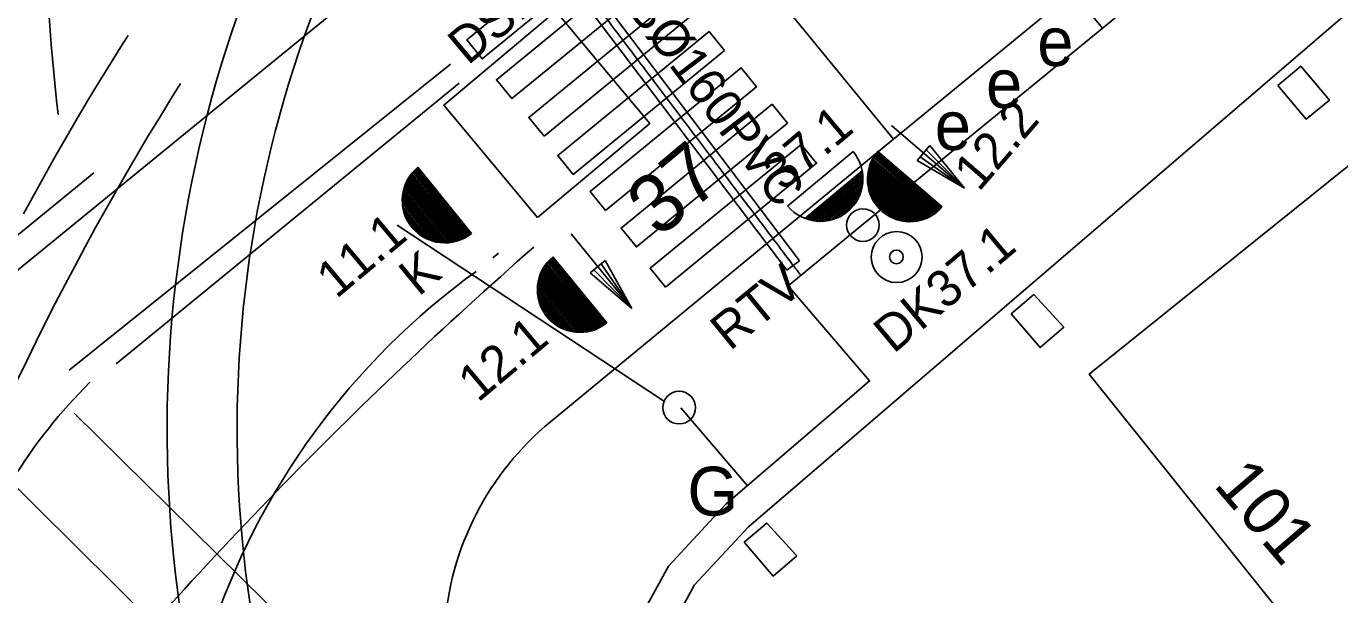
# Model space of a CAD drawing. Extents: x 81617 to 82144, y 454649 to 455150.
# Drawn here: x 81850.79 to 81877.73, y 454892.85 to 454904.5 of the extents above; entities that cross this region are included whole.
import ezdxf

# ---------------------------------------------------------------- set-up
doc = ezdxf.new("R2010")
doc.units = 0
for name, color, linetype in [('B-WE-OG-TOPOGRAFIE-G', 7, 'Continuous'), ('B-WE-VW-MARKERING-G', 7, 'Continuous'), ('N-OI-KL-VRI_KABELGEUL-G', 7, 'Continuous'), ('N-OI-KL-VRI_LUS_DETECTIE_SELECTIEF-G', 7, 'Continuous'), ('N-OI-KL-VRI_LUS_DETECTIE_SELECTIEF-T18', 7, 'Continuous'), ('N-OI-KL-VRI_MANTELBUIS-G', 7, 'Continuous'), ('N-OI-KL-VRI_MANTELBUIS-T18', 7, 'Continuous'), ('N-WE-VW-VRI_ARMATUUR-S', 7, 'Continuous'), ('N-WE-VW-VRI_ARMATUUR-T18', 7, 'Continuous'), ('N-WE-VW-VRI_LIGGER-G', 7, 'Continuous'), ('N-WE-VW-VRI_MAST-S', 7, 'Continuous'), ('N-WE-VW-VRI_RICHTINGNUMMER-T25', 7, 'Continuous')]:
    doc.layers.add(name, color=color, linetype=linetype)

msp = doc.modelspace()

# ---------------------------------------------------------------- linework, layer by layer
at = {"layer": 'B-WE-OG-TOPOGRAFIE-G'}
for p, q in [((81881.705, 454912.935), (81868.159, 454901.847)), ((81884.598, 454910.533), (81865.6, 454894.244)), ((81865.6, 454894.244), (81864.496, 454893.051)), ((81864.496, 454893.051), (81863.715, 454891.626))]:
    msp.add_line(p, q, dxfattribs=at)
for points in [[(81905.797, 454910.826), (81895.907, 454902.577), (81894.356, 454904.415), (81878.095, 454890.513), (81872.591, 454897.372), (81877.883, 454901.619), (81888.858, 454911.006), (81888.57, 454911.351)], [(81852.878, 454904.311), (81852.766, 454904.134), (81852.528, 454903.754), (81852.294, 454903.373), (81852.062, 454902.99), (81851.834, 454902.607), (81851.608, 454902.221), (81851.383, 454901.831), (81850.948, 454901.054), (81850.733, 454900.659)], [(81876.463, 454903.285), (81876.929, 454903.679), (81877.517, 454902.984), (81877.039, 454902.598), (81876.463, 454903.285)], [(81853.953, 454903.327), (81853.748, 454902.998), (81853.519, 454902.626), (81853.293, 454902.252), (81853.07, 454901.877), (81852.849, 454901.5), (81852.631, 454901.122), (81852.204, 454900.36), (81851.995, 454899.977), (81851.789, 454899.592), (81851.585, 454899.206), (81851.384, 454898.818), (81851.186, 454898.429), (81850.991, 454898.038), (81850.799, 454897.646), (81850.61, 454897.253), (81850.423, 454896.858), (81850.24, 454896.461), (81850.058, 454896.06), (81849.702, 454895.254), (81849.356, 454894.442), (81849.019, 454893.625), (81848.691, 454892.804)], [(81868.159, 454901.847), (81861.541, 454896.395)], [(81871.452, 454899), (81872.069, 454898.33), (81871.583, 454897.914), (81870.991, 454898.605), (81871.452, 454899)], [(81865.517, 454893.926), (81865.982, 454894.319), (81866.594, 454893.648), (81866.107, 454893.233), (81865.517, 454893.926)]]:
    msp.add_lwpolyline(points, dxfattribs=at)
for centre, radius, start, end in [((81879.363, 454896.235), 25.685, 143.017, 194.1581), ((81879.363, 454896.235), 24.25, 143.017, 194.1581), ((81865.356, 454891.764), 6, 129.48, 223.0627)]:
    msp.add_arc(centre, radius, start, end, dxfattribs=at)
at = {"layer": 'B-WE-VW-MARKERING-G'}
for p, q in [((81868.576, 454902.188), (81862.556, 454909.542)), ((81852.173, 454901.495), (81847.644, 454897.796)), ((81860.476, 454899.85), (81860.356, 454899.752)), ((81859.578, 454888.893), (81851.77, 454896.571)), ((81860.984, 454884.776), (81850.084, 454895.546))]:
    msp.add_line(p, q, dxfattribs=at)
for points in [[(81863.241, 454906.37), (81860.141, 454903.832), (81859.824, 454904.219), (81862.925, 454906.757)], [(81863.851, 454905.554), (81860.75, 454903.017), (81860.433, 454903.404), (81863.534, 454905.941)], [(81861.412, 454902.246), (81864.512, 454904.784), (81864.195, 454905.17), (81861.095, 454902.633)], [(81865.109, 454904.003), (81862.009, 454901.465), (81861.692, 454901.852), (81864.793, 454904.39)], [(81862.669, 454900.723), (81865.769, 454903.261), (81865.453, 454903.648), (81862.352, 454901.11)], [(81866.405, 454902.515), (81863.305, 454899.977), (81862.988, 454900.364), (81866.088, 454902.901)], [(81863.9, 454899.153), (81867, 454901.691), (81866.684, 454902.078), (81863.583, 454899.54)]]:
    msp.add_lwpolyline(points, close=True, dxfattribs=at)
for points in [[(81857.965, 454905.504), (81847.346, 454896.846)], [(81859.492, 454903.724), (81851.668, 454897.452)], [(81859.666, 454903.336), (81852.632, 454897.581)]]:
    msp.add_lwpolyline(points, dxfattribs=at)
for centre, radius, start, end in [((81891.158, 454907.365), 39.987, 173.5249, 186.7077), ((81920.451, 454832.229), 90, 131.17648, 140.46049), ((81868.809, 454887.325), 15, 125.8906, 161.8334), ((81859.635, 454889.585), 10.719, 134.6953, 161.9917)]:
    msp.add_arc(centre, radius, start, end, dxfattribs=at)
at = {"layer": 'N-OI-KL-VRI_KABELGEUL-G'}
msp.add_line((81872.26, 454905.203), (81872.866, 454904.461), dxfattribs=at)
for points in [[(81868.039, 454900.514), (81884.291, 454913.804)], [(81868.039, 454900.514), (81866.417, 454899.179)], [(81866.417, 454899.179), (81868.086, 454897.232), (81867.77, 454896.961), (81865.148, 454894.713), (81863.965, 454893.434), (81863.103, 454891.862), (81862.654, 454889.993), (81862.638, 454888.354), (81862.929, 454886.524), (81867.816, 454881.297)], [(81864.213, 454896.678), (81865.58, 454895.083)]]:
    msp.add_lwpolyline(points, dxfattribs=at)
msp.add_open_spline([(81966.954, 454994.044), (81954.516, 454984.42), (81942.079, 454974.796), (81941.008, 454974.125), (81939.937, 454973.455), (81933.631, 454968.575), (81927.325, 454963.696), (81926.798, 454963.288), (81926.621, 454962.646), (81926.355, 454961.682), (81926.09, 454960.718), (81925.901, 454960.035), (81925.325, 454959.623), (81922.434, 454957.557), (81919.543, 454955.49), (81917.87, 454954.23), (81916.197, 454952.97), (81913.406, 454950.849), (81910.615, 454948.728), (81908.564, 454947.145), (81906.513, 454945.562), (81905.944, 454945.123), (81905.225, 454945.147), (81904.815, 454945.16), (81904.405, 454945.174), (81903.693, 454945.197), (81903.126, 454944.765), (81893.683, 454937.565), (81884.239, 454930.365), (81883.469, 454929.731), (81882.698, 454929.096), (81879.285, 454926.178), (81875.872, 454923.259), (81872.421, 454920.321), (81868.97, 454917.382), (81867.082, 454915.724), (81865.195, 454914.067), (81863.45, 454912.271), (81861.704, 454910.475), (81860.838, 454909.482), (81859.972, 454908.49), (81859.86, 454908.361), (81859.97, 454908.23), (81860.094, 454908.077), (81860.218, 454907.925), (81863.368, 454903.762), (81866.518, 454899.599), (81866.598, 454899.497), (81866.679, 454899.395)], degree=4, dxfattribs=at)
at = {"layer": 'N-OI-KL-VRI_LUS_DETECTIE_SELECTIEF-G'}
msp.add_lwpolyline([(81861.276, 454900.581), (81859.351, 454902.881), (81861.651, 454904.806), (81863.578, 454902.506)], close=True, dxfattribs=at)
at = {"layer": 'N-OI-KL-VRI_MANTELBUIS-G'}
msp.add_lwpolyline([(81866.39, 454899.502), (81860.17, 454907.723), (81860.426, 454907.917), (81866.646, 454899.695), (81866.39, 454899.502)], dxfattribs=at)
at = {"layer": 'N-WE-VW-VRI_ARMATUUR-S'}
for p, q in [((81868.537, 454902.464), (81870.032, 454901.18)), ((81869.063, 454901.747), (81869.322, 454902.054)), ((81869.249, 454901.967), (81870.032, 454901.18)), ((81869.322, 454902.054), (81870.032, 454901.18)), ((81867.75, 454901.932), (81866.404, 454900.815)), ((81869.368, 454900.62), (81868.108, 454901.702)), ((81869.394, 454900.637), (81868.122, 454901.732)), ((81869.422, 454900.655), (81868.135, 454901.758)), ((81869.445, 454900.672), (81868.148, 454901.785)), ((81869.469, 454900.691), (81868.164, 454901.814)), ((81869.493, 454900.713), (81868.18, 454901.838)), ((81869.515, 454900.734), (81868.195, 454901.864)), ((81869.536, 454900.755), (81868.214, 454901.887)), ((81869.558, 454900.776), (81868.232, 454901.911)), ((81869.578, 454900.798), (81868.251, 454901.937)), ((81870.032, 454901.18), (81869.063, 454901.747)), ((81869.127, 454901.823), (81870.032, 454901.18)), ((81859.713, 454900.13), (81858.658, 454901.435)), ((81859.744, 454900.143), (81858.675, 454901.459)), ((81859.771, 454900.157), (81858.694, 454901.483)), ((81859.796, 454900.17), (81858.715, 454901.508)), ((81859.824, 454900.186), (81858.734, 454901.529)), ((81859.85, 454900.203), (81858.755, 454901.55)), ((81859.875, 454900.219), (81858.776, 454901.572)), ((81859.899, 454900.238), (81858.801, 454901.593)), ((81859.923, 454900.255), (81858.823, 454901.613)), ((81867.934, 454901.539), (81866.756, 454900.563)), ((81867.941, 454901.505), (81866.788, 454900.55)), ((81867.946, 454901.47), (81866.821, 454900.538)), ((81867.949, 454901.433), (81866.856, 454900.529)), ((81869.12, 454900.519), (81868.045, 454901.442)), ((81869.156, 454900.528), (81868.049, 454901.478)), ((81869.189, 454900.539), (81868.053, 454901.514)), ((81869.222, 454900.55), (81868.061, 454901.546)), ((81869.253, 454900.563), (81868.069, 454901.579)), ((81869.284, 454900.576), (81868.077, 454901.612)), ((81869.314, 454900.589), (81868.087, 454901.643)), ((81869.344, 454900.605), (81868.099, 454901.67)), ((81859.423, 454900.062), (81858.53, 454901.164)), ((81859.46, 454900.065), (81858.54, 454901.199)), ((81859.495, 454900.069), (81858.552, 454901.233)), ((81859.529, 454900.074), (81858.566, 454901.263)), ((81859.563, 454900.082), (81858.578, 454901.295)), ((81859.594, 454900.089), (81858.593, 454901.326)), ((81859.626, 454900.098), (81858.608, 454901.354)), ((81859.655, 454900.106), (81858.622, 454901.381)), ((81859.686, 454900.119), (81858.639, 454901.408)), ((81867.952, 454901.396), (81866.894, 454900.521)), ((81867.951, 454901.356), (81866.931, 454900.513)), ((81867.948, 454901.317), (81866.972, 454900.506)), ((81867.944, 454901.275), (81867.015, 454900.5)), ((81867.939, 454901.23), (81867.059, 454900.5)), ((81867.932, 454901.182), (81867.107, 454900.502)), ((81869.083, 454900.509), (81868.042, 454901.404)), ((81869.005, 454900.499), (81868.042, 454901.326)), ((81869.046, 454900.503), (81868.043, 454901.365)), ((81868.963, 454900.496), (81868.044, 454901.282)), ((81868.92, 454900.493), (81868.052, 454901.238)), ((81868.87, 454900.494), (81868.059, 454901.19)), ((81859.172, 454900.083), (81858.5, 454900.912)), ((81859.264, 454900.068), (81858.501, 454901.006)), ((81859.22, 454900.074), (81858.501, 454900.962)), ((81859.307, 454900.063), (81858.508, 454901.049)), ((81859.347, 454900.061), (81858.514, 454901.089)), ((81859.385, 454900.061), (81858.522, 454901.127)), ((81867.916, 454901.134), (81867.156, 454900.505)), ((81867.901, 454901.081), (81867.212, 454900.511)), ((81867.877, 454901.022), (81867.275, 454900.521)), ((81867.845, 454900.957), (81867.345, 454900.543)), ((81868.821, 454900.499), (81868.071, 454901.143)), ((81868.764, 454900.509), (81868.089, 454901.087)), ((81868.705, 454900.52), (81868.109, 454901.028)), ((81868.634, 454900.541), (81868.14, 454900.962)), ((81868.547, 454900.576), (81868.187, 454900.882)), ((81859.125, 454900.097), (81858.503, 454900.865)), ((81859.07, 454900.114), (81858.508, 454900.807)), ((81859.014, 454900.138), (81858.519, 454900.745)), ((81858.949, 454900.171), (81858.539, 454900.674)), ((81867.795, 454900.877), (81867.432, 454900.576)), ((81867.682, 454900.744), (81867.584, 454900.66)), ((81868.395, 454900.664), (81868.297, 454900.748)), ((81858.869, 454900.222), (81858.57, 454900.587)), ((81858.737, 454900.337), (81858.655, 454900.436)), ((81861.965, 454900.244), (81863.211, 454898.717)), ((81862.431, 454898.272), (81861.394, 454899.54)), ((81862.458, 454898.282), (81861.408, 454899.569)), ((81862.487, 454898.294), (81861.427, 454899.597)), ((81862.517, 454898.307), (81861.445, 454899.62)), ((81862.543, 454898.32), (81861.463, 454899.645)), ((81862.57, 454898.335), (81861.484, 454899.67)), ((81862.597, 454898.352), (81861.503, 454899.691)), ((81862.622, 454898.368), (81861.523, 454899.713)), ((81862.648, 454898.385), (81861.546, 454899.733)), ((81862.672, 454898.402), (81861.568, 454899.754)), ((81862.696, 454898.421), (81861.591, 454899.776)), ((81862.357, 454899.446), (81862.666, 454899.702)), ((81862.579, 454899.63), (81863.211, 454898.717)), ((81862.666, 454899.702), (81863.211, 454898.717)), ((81862.158, 454898.223), (81861.292, 454899.288)), ((81862.196, 454898.226), (81861.301, 454899.324)), ((81862.233, 454898.229), (81861.311, 454899.36)), ((81862.268, 454898.234), (81861.322, 454899.394)), ((81862.302, 454898.239), (81861.335, 454899.425)), ((81862.335, 454898.246), (81861.348, 454899.456)), ((81862.368, 454898.254), (81861.362, 454899.487)), ((81862.4, 454898.262), (81861.378, 454899.515)), ((81863.211, 454898.717), (81862.357, 454899.446)), ((81862.433, 454899.509), (81863.211, 454898.717)), ((81861.945, 454898.246), (81861.27, 454899.075)), ((81862.037, 454898.232), (81861.271, 454899.168)), ((81861.994, 454898.237), (81861.272, 454899.123)), ((81861.898, 454898.259), (81861.273, 454899.026)), ((81862.079, 454898.228), (81861.277, 454899.211)), ((81862.121, 454898.224), (81861.285, 454899.249)), ((81861.844, 454898.28), (81861.282, 454898.968)), ((81861.787, 454898.301), (81861.291, 454898.906)), ((81861.721, 454898.334), (81861.31, 454898.836)), ((81861.642, 454898.384), (81861.342, 454898.749)), ((81861.508, 454898.497), (81861.427, 454898.597))]:
    msp.add_line(p, q, dxfattribs=at)
for centre, radius in [((81868.642, 454899.77), 0.522), ((81868.637, 454899.773), 0.141)]:
    msp.add_circle(centre, radius, dxfattribs=at)
for centre, start, end in [((81867.077, 454901.374), 219.6416, 39.6416), ((81868.916, 454901.367), 139.3607, 319.3607), ((81859.373, 454900.934), 129.0211, 309.0211), ((81862.145, 454899.098), 129.1939, 309.1939)]:
    msp.add_arc(centre, 0.873, start, end, dxfattribs=at)
at = {"layer": 'N-WE-VW-VRI_LIGGER-G'}
msp.add_line((81863.883, 454896.809), (81858.397, 454900.422), dxfattribs=at)
at = {"layer": 'N-WE-VW-VRI_MAST-S'}
for centre in [(81867.95, 454900.425), (81864.18, 454896.684)]:
    msp.add_circle(centre, 0.335, dxfattribs=at)

# ---------------------------------------------------------------- texts
at = {"layer": 'B-WE-OG-TOPOGRAFIE-G'}
for s, p in [('e', (81871.525, 454903.685)), ('e', (81870.474, 454902.825)), ('e', (81869.423, 454901.965)), ('G', (81864.35, 454894.473))]:
    msp.add_text(s, height=1, dxfattribs=at).set_placement(p)
msp.add_text('101', height=1, rotation=310.5847, dxfattribs=at).set_placement((81875.121, 454895.09))
at = {"layer": 'N-OI-KL-VRI_LUS_DETECTIE_SELECTIEF-T18'}
msp.add_text('DS11.1', height=0.75, rotation=40.0471, dxfattribs=at).set_placement((81859.846, 454903.685))
at = {"layer": 'N-OI-KL-VRI_MANTELBUIS-T18'}
msp.add_text('2xMB%%C160PVC', height=0.75, rotation=307.11, dxfattribs=at).set_placement((81861.933, 454906.38))
at = {"layer": 'N-WE-VW-VRI_ARMATUUR-S'}
for s, p in [('K', (81858.834, 454898.947)), ('RTV', (81865.221, 454897.833))]:
    msp.add_text(s, height=0.75, rotation=39.3238, dxfattribs=at).set_placement(p)
at = {"layer": 'N-WE-VW-VRI_ARMATUUR-T18'}
for s, rotation, p in [('37.1', 40.0117, (81866.305, 454901.103)), ('12.2', 49.2031, (81870.326, 454901.09)), ('11.1', 40.0117, (81857.149, 454898.902)), ('DK37.1', 40.0117, (81868.577, 454897.775)), ('12.1', 40.0117, (81860.053, 454896.776))]:
    msp.add_text(s, height=0.75, rotation=rotation, dxfattribs=at).set_placement(p)
at = {"layer": 'N-WE-VW-VRI_RICHTINGNUMMER-T25'}
msp.add_text('37', height=1.2, rotation=40, dxfattribs=at).set_placement((81863.766, 454900.143))

doc.saveas('drawing.dxf')
